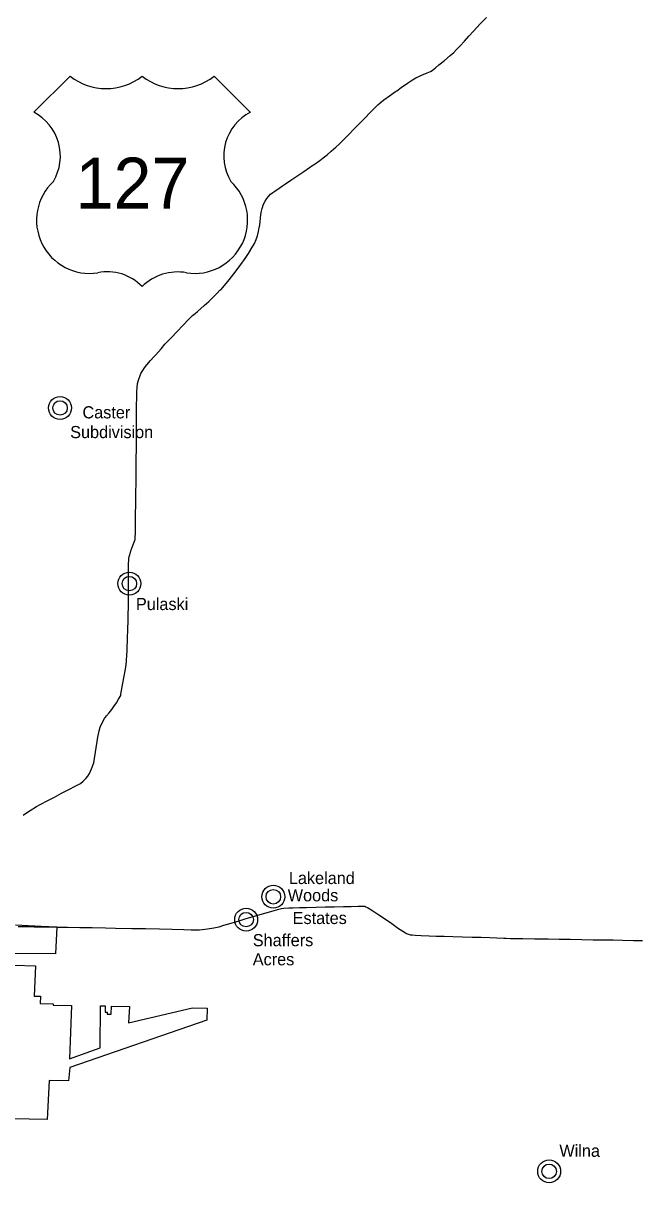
# Model space of a CAD drawing. Extents: x -66 to 795, y 0 to 440.
# Drawn here: x 383.6 to 443.5, y 105.6 to 219 of the extents above; entities that cross this region are included whole.
import ezdxf

# ---------------------------------------------------------------- set-up
doc = ezdxf.new("R2010")
doc.units = 0
for name, color, linetype in [('DV_X_Corp_Line', 7, 'Continuous'), ('GM_X_State_Route', 7, 'Continuous'), ('GM_X_US_Route', 7, 'Continuous'), ('PV_P_Text', 7, 'Continuous')]:
    doc.layers.add(name, color=color, linetype=linetype)

msp = doc.modelspace()

# ---------------------------------------------------------------- linework, layer by layer
at = {"layer": 'DV_X_Corp_Line'}
for points in [[(382.85, 130.82), (385.37, 130.7), (386.88, 130.64), (386.76, 127.99), (382.72, 128.02)], [(382.68, 126.88), (384.8, 126.82), (384.67, 123.85), (385.28, 123.84), (385.25, 123.15), (386.54, 123.12), (386.54, 122.98), (388.34, 122.95), (388.14, 117.72), (390.22, 118.48), (391.12, 118.81), (391.18, 122.92), (391.35, 122.91), (391.62, 122.91), (391.61, 122.3), (391.81, 122.28), (391.81, 122.09), (392.2, 122.1), (392.24, 122.89), (393.99, 122.85), (393.92, 121.25), (400.17, 122.71), (401.59, 122.68), (401.55, 121.51), (388.17, 116.89), (388.05, 115.56), (386.14, 115.62), (385.94, 111.78), (382.44, 111.85)]]:
    msp.add_lwpolyline(points, dxfattribs=at)
for centre, radius in [((387.21, 181.39), 1.12), ((387.21, 181.39), 0.71), ((393.99, 164.21), 1.12), ((393.99, 164.21), 0.71), ((408.07, 133.58), 1.12), ((408.07, 133.58), 0.71), ((405.41, 131.34), 1.12), ((405.41, 131.34), 0.71), ((435.05, 106.72), 1.12), ((435.05, 106.72), 0.71)]:
    msp.add_circle(centre, radius, dxfattribs=at)
at = {"layer": 'GM_X_State_Route'}
for points in [[(386.86, 130.6), (387.93, 130.59), (389.15, 130.57), (390.36, 130.56), (391.66, 130.53), (392.62, 130.52), (394.23, 130.48), (395.56, 130.47), (396.93, 130.44), (398.17, 130.42), (399.33, 130.36), (400.04, 130.34), (400.54, 130.33), (400.84, 130.33), (401.11, 130.37), (401.63, 130.44), (402.25, 130.54), (402.57, 130.6), (402.78, 130.65), (403.23, 130.79), (403.94, 131), (404.72, 131.23), (405.41, 131.44), (408.07, 132.21), (408.48, 132.34), (408.73, 132.41), (408.87, 132.44), (409.09, 132.45), (409.59, 132.49), (409.98, 132.51), (410.62, 132.53), (411.33, 132.54), (412.25, 132.56), (413.15, 132.58), (414.07, 132.6), (414.95, 132.62), (415.61, 132.64), (415.68, 132.64), (416.38, 132.67), (416.85, 132.66), (417.01, 132.65), (417.13, 132.6), (417.27, 132.54), (417.46, 132.44), (417.81, 132.2), (418.39, 131.82), (419.03, 131.39), (419.65, 130.97), (420.33, 130.49), (420.9, 130.11), (421.09, 129.99), (421.28, 129.92), (421.44, 129.87), (421.65, 129.85), (421.94, 129.83), (422.54, 129.8), (423.31, 129.77), (424, 129.74), (424.79, 129.72), (425.64, 129.69), (426.58, 129.67), (427.51, 129.64), (428.39, 129.61), (429.24, 129.59), (429.93, 129.56), (430.63, 129.54), (430.83, 129.53), (430.84, 129.53)], [(383.12, 130.68), (383.14, 130.68), (383.89, 130.67), (384.57, 130.66), (384.68, 130.65)], [(384.68, 130.65), (385.36, 130.64), (386.06, 130.63), (386.86, 130.6)], [(430.84, 129.53), (431.28, 129.51), (432.48, 129.48), (433.64, 129.47), (434.95, 129.45), (436.03, 129.43), (437.11, 129.42), (438.26, 129.39), (439.35, 129.38), (439.9, 129.37), (440.29, 129.37), (441.32, 129.35), (442.24, 129.33), (443.29, 129.31), (444.17, 129.3)]]:
    msp.add_lwpolyline(points, dxfattribs=at)
at = {"layer": 'GM_X_US_Route'}
for points in [[(408.97, 203.12), (409.25, 203.31), (409.79, 203.68), (410.38, 204.08), (411.04, 204.52), (411.62, 204.92), (411.95, 205.13), (412.07, 205.21), (412.61, 205.59), (412.95, 205.85), (413.33, 206.16), (413.74, 206.5), (414.19, 206.9), (414.52, 207.19), (414.9, 207.57), (415.43, 208.1), (415.98, 208.68), (416.5, 209.21), (417.01, 209.75), (417.53, 210.28), (418, 210.76), (418.29, 211.05), (418.52, 211.25), (418.89, 211.53), (419.44, 211.93), (420.01, 212.33), (420.14, 212.42), (420.57, 212.73), (421.18, 213.16), (421.68, 213.48), (422.02, 213.68), (422.38, 213.86), (422.72, 214.01), (423.12, 214.17), (423.43, 214.3), (423.61, 214.41), (423.94, 214.67), (424.27, 214.94), (424.81, 215.39), (425.38, 215.86), (425.73, 216.16), (426, 216.44), (426.36, 216.82), (426.77, 217.27), (427.21, 217.76), (427.66, 218.25), (428.31, 218.96), (428.91, 219.6)], [(405.43, 196.2), (405.63, 196.51), (405.96, 197.04), (406.22, 197.49), (406.38, 197.87), (406.52, 198.24), (406.61, 198.65), (406.7, 199.05), (406.71, 199.11), (406.77, 199.55), (406.83, 200.03), (406.89, 200.52), (406.98, 200.91), (407.12, 201.32), (407.27, 201.63), (407.43, 201.87), (407.6, 202.09), (407.8, 202.3), (408.01, 202.46), (408.22, 202.61), (408.64, 202.89), (408.97, 203.12), (408.97, 203.12)], [(396.38, 186.39), (396.42, 186.43), (396.57, 186.6), (397.09, 187.19), (397.47, 187.64), (398.08, 188.26), (398.65, 188.88), (399.21, 189.45), (399.81, 190.08), (400.18, 190.42), (400.41, 190.64), (400.65, 190.84), (401.31, 191.42), (401.76, 191.82), (402.15, 192.2), (402.57, 192.61), (402.85, 192.9), (402.92, 192.96), (403.29, 193.37), (403.74, 193.91), (404.2, 194.5), (404.53, 194.93), (404.89, 195.43), (405.3, 196), (405.43, 196.2), (405.43, 196.2)], [(394.71, 182.38), (394.71, 182.39), (394.71, 182.52), (394.71, 182.98), (394.71, 183.03), (394.75, 183.37), (394.8, 183.77), (394.91, 184.2), (395, 184.48), (395.12, 184.77), (395.29, 185.05), (395.48, 185.33), (395.69, 185.61), (396.07, 186.04), (396.38, 186.39)], [(394.59, 169.71), (394.59, 169.9), (394.59, 169.96), (394.6, 171.03), (394.61, 171.91), (394.62, 172.95), (394.64, 174.19), (394.66, 175.25), (394.67, 176.32), (394.68, 177.51), (394.68, 178.64), (394.68, 179.63), (394.7, 180.78), (394.7, 181.68), (394.71, 182.38)], [(393.89, 161.78), (393.89, 162.01), (393.89, 162.11), (393.9, 162.51), (393.9, 162.77), (393.9, 163.35), (393.9, 163.47), (393.92, 164.08), (393.92, 164.29), (393.91, 164.58), (393.92, 164.81), (393.92, 165.26), (393.92, 165.31), (393.92, 165.78), (393.92, 166.14), (393.92, 166.26), (393.93, 166.39), (393.95, 166.62), (393.98, 166.85), (394.03, 167.04), (394.07, 167.19), (394.09, 167.26), (394.14, 167.4), (394.24, 167.68), (394.34, 167.93), (394.47, 168.25), (394.54, 168.51), (394.57, 168.74), (394.59, 169.12), (394.59, 169.71)], [(393.72, 156.83), (393.72, 156.9), (393.73, 157.01), (393.78, 157.84), (393.81, 158.83), (393.85, 159.75), (393.87, 160.58), (393.88, 161.29), (393.88, 161.35), (393.89, 161.78)], [(383.6, 141.57), (384.04, 141.85), (384.56, 142.19), (384.64, 142.25), (384.91, 142.42), (385.26, 142.6), (386.01, 142.99), (386.65, 143.33), (387.35, 143.7), (388.08, 144.08), (388.68, 144.39), (389.2, 144.67), (389.46, 144.89), (389.72, 145.14), (389.93, 145.39), (390.09, 145.65), (390.3, 146.09), (390.5, 146.68), (390.91, 149.19), (391.02, 149.82), (391.14, 150.17), (391.32, 150.58), (391.56, 151), (391.74, 151.27), (392, 151.57), (392.27, 151.89), (392.48, 152.2), (392.72, 152.56), (392.94, 152.92), (393.14, 153.27), (393.17, 153.41), (393.3, 154.11), (393.46, 154.99), (393.61, 155.85), (393.68, 156.31), (393.7, 156.6), (393.72, 156.83)]]:
    msp.add_lwpolyline(points, dxfattribs=at)
at = {"layer": 'PV_P_Text'}
for p, q in [((388.19, 213.85), (384.64, 210.31)), ((405.82, 210.31), (402.28, 213.85))]:
    msp.add_line(p, q, dxfattribs=at)
for centre, radius, start, end in [((391.71, 218.33), 5.7, 231.813, 308.187), ((398.76, 218.33), 5.7, 231.813, 308.187), ((382.42, 206.03), 4.82, 329.1175, 62.6108), ((408.04, 206.03), 4.82, 117.3892, 210.8825), ((390.11, 199.75), 5.2, 133.0046, 278.7282), ((400.36, 199.75), 5.2, 261.2718, 46.9954), ((391.85, 190.06), 4.65, 43.4177, 101.8742), ((398.71, 189.75), 4.94, 79.9613, 134.7468)]:
    msp.add_arc(centre, radius, start, end, dxfattribs=at)

# ---------------------------------------------------------------- texts
at = {"layer": 'DV_X_Corp_Line'}
for s, height, p in [('Caster', 1.188, (389.4, 180.37)), ('Subdivision', 1.1875, (388.2, 178.44)), ('Pulaski', 1.188, (394.63, 161.62)), ('Lakeland', 1.188, (409.59, 134.82)), ('Woods', 1.188, (409.48, 133.13)), ('Estates', 1.188, (409.96, 130.91)), ('Shaffers', 1.188, (406.06, 128.74)), ('Acres', 1.188, (406.06, 126.87)), ('Wilna', 1.188, (436.05, 108.14))]:
    msp.add_text(s, height=height, rotation=0, dxfattribs=at).set_placement(p)
at = {"layer": 'PV_P_Text'}
msp.add_text('127', height=4.987, dxfattribs=at).set_placement((388.73, 200.89))

doc.saveas('drawing.dxf')
